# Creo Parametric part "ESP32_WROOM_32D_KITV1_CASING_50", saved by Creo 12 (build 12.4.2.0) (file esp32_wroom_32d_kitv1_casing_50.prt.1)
Units: Custom; MM, KILOGRAM, SECS

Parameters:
  PTC_WM_ITERATION = "0"
  PTC_WM_VERSION = "-.0"
  PTC_WM_LIFECYCLE_STATE = "In Work"
  PTC_WM_LIFECYCLE = "MO_CADDocument"
  PTC_WM_CREATED_BY = "Maximilian Roepper (Z0017RMS: MO)"
  PTC_WM_CREATED_ON = "18-Sep-26 11:36:42 AM"
  PTC_WM_MODIFIED_BY = "Maximilian Roepper (Z0017RMS: MO)"
  PTC_WM_MODIFIED_ON = "18-Sep-26 11:36:46 AM"
  PDMLINKNUMBER = "PDM000071454824"
  PTC_WM_NAME = "esp32_wroom_32d_kitv1_casing_50.prt"
  PTC_WM_NUMBER = "PDM000071454824"

Other parameters: WEIGHT, WEIGHT_FACTOR, WEIGHT_ADD, _MASS_TEMP, _DIFF_TEMP, MC_ERRORS, SUPPLIER

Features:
  1. coordinate system
  2. datum plane "PRT_YZ"
  3. datum plane "PRT_XY"
  4. datum plane "PRT_XZ"
  5. coordinate system
  6. datum axis
  7. datum axis
  8. datum axis
  9. coordinate system
  10. imported feature
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
Other named items: PRT, SIEMENS_MO, DRW_VIEW_ORG, PRT_X, PRT_Y, PRT_Z, CS0, ROUGH_GROB

Layers: 00_STD_CSYS-KSYS, 01_STD_PLANES-EBENEN, 02_STD_AXES-ACHSEN, 03_STD_CSYS-KSYS, 24_IMPORT_FEAT-IMPORT_KE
